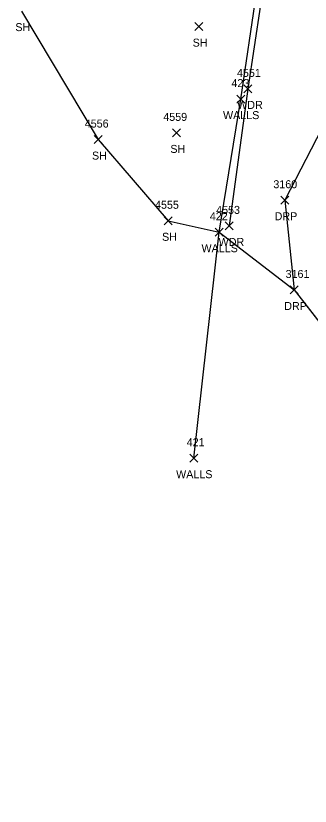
# Model space of a CAD drawing. Extents: x 1509053 to 1511576, y 400838 to 402572.
# Drawn here: x 1509486.6 to 1509560.1, y 401706.7 to 401904.1 of the extents above; entities that cross this region are included whole.
import ezdxf

# ---------------------------------------------------------------- set-up
doc = ezdxf.new("R2010")
doc.units = 0
for name, color, linetype in [('L_A', 7, 'Continuous'), ('L_I', 7, 'Continuous'), ('L_TIC', 7, 'Continuous'), ('LAWA', 7, 'Continuous'), ('LSOGP', 7, 'Continuous'), ('LWS', 7, 'Continuous'), ('R_A', 7, 'Continuous'), ('R_I', 7, 'Continuous'), ('R_TIC', 7, 'Continuous'), ('RDP', 7, 'Continuous')]:
    doc.layers.add(name, color=color, linetype=linetype)

msp = doc.modelspace()

# ---------------------------------------------------------------- linework, layer by layer
at = {"layer": 'L_TIC'}
for points in [[(1509531.26, 401900.37), (1509533.26, 401902.37)], [(1509533.26, 401900.37), (1509531.26, 401902.37)], [(1509543.51, 401884.82), (1509545.51, 401886.82)], [(1509545.51, 401884.82), (1509543.51, 401886.82)], [(1509541.8, 401882.27), (1509543.8, 401884.27)], [(1509543.8, 401882.27), (1509541.8, 401884.27)], [(1509525.69, 401873.83), (1509527.69, 401875.83)], [(1509527.69, 401873.83), (1509525.69, 401875.83)], [(1509506.12, 401872.16), (1509508.12, 401874.16)], [(1509508.12, 401872.16), (1509506.12, 401874.16)], [(1509523.62, 401851.88), (1509525.62, 401853.88)], [(1509525.62, 401851.88), (1509523.62, 401853.88)], [(1509538.88, 401850.6), (1509540.88, 401852.6)], [(1509540.88, 401850.6), (1509538.88, 401852.6)], [(1509536.41, 401849.03), (1509538.41, 401851.03)], [(1509538.41, 401849.03), (1509536.41, 401851.03)], [(1509530.07, 401792.59), (1509532.07, 401794.59)], [(1509532.07, 401792.59), (1509530.07, 401794.59)]]:
    msp.add_lwpolyline(points, dxfattribs=at)
at = {"layer": 'LAWA'}
msp.add_lwpolyline([(1509549.28, 401917.4), (1509544.51, 401885.82), (1509539.88, 401851.6)], dxfattribs=at)
at = {"layer": 'LSOGP'}
msp.add_lwpolyline([(1509487.97, 401905.25), (1509507.12, 401873.16), (1509524.62, 401852.88), (1509537.41, 401850.03), (1509556.14, 401835.6), (1509559.91, 401830.74), (1509563.69, 401825.89)], dxfattribs=at)
at = {"layer": 'LWS'}
msp.add_lwpolyline([(1509531.07, 401793.59), (1509537.41, 401850.03), (1509542.8, 401883.27), (1509546.66, 401909.78), (1509550.53, 401940.5), (1509554.91, 401970.83)], dxfattribs=at)
at = {"layer": 'R_TIC'}
for points in [[(1509552.74, 401857.01), (1509554.74, 401859.01)], [(1509554.74, 401857.01), (1509552.74, 401859.01)], [(1509555.14, 401834.6), (1509557.14, 401836.6)], [(1509557.14, 401834.6), (1509555.14, 401836.6)]]:
    msp.add_lwpolyline(points, dxfattribs=at)
at = {"layer": 'RDP'}
msp.add_lwpolyline([(1509572.43, 401913.76), (1509571.87, 401895.84), (1509563.03, 401875.91), (1509553.74, 401858.01), (1509556.14, 401835.6), (1509571.23, 401816.18), (1509583.76, 401803.06), (1509589.35, 401790.3), (1509589.12, 401773.24), (1509584.51, 401748.72), (1509580.76, 401730.09), (1509580.7, 401706.68)], dxfattribs=at)

# ---------------------------------------------------------------- texts
at = {"layer": 'L_A'}
for s, p in [('SH', (1509486.46, 401900.25)), ('SH', (1509530.75, 401896.37)), ('WDR', (1509541.87, 401880.82)), ('WALLS', (1509538.34, 401878.27)), ('SH', (1509525.18, 401869.83)), ('SH', (1509505.61, 401868.16)), ('SH', (1509523.11, 401847.88)), ('WDR', (1509537.24, 401846.6)), ('WALLS', (1509532.96, 401845.03)), ('WALLS', (1509526.62, 401788.59))]:
    msp.add_text(s, height=2, dxfattribs=at).set_placement(p)
at = {"layer": 'L_I'}
for s, p in [('4551', (1509541.82, 401888.82)), ('423', (1509540.44, 401886.27)), ('4559', (1509523.42, 401877.83)), ('4556', (1509503.81, 401876.16)), ('4555', (1509521.36, 401855.88)), ('4553', (1509536.62, 401854.6)), ('422', (1509535.05, 401853.03)), ('421', (1509529.28, 401796.59))]:
    msp.add_text(s, height=2, dxfattribs=at).set_placement(p)
at = {"layer": 'R_A'}
for p in [(1509551.23, 401853.01), (1509553.63, 401830.6)]:
    msp.add_text('DRP', height=2, dxfattribs=at).set_placement(p)
at = {"layer": 'R_I'}
for s, p in [('3160', (1509550.91, 401861.01)), ('3161', (1509553.97, 401838.6))]:
    msp.add_text(s, height=2, dxfattribs=at).set_placement(p)

doc.saveas('drawing.dxf')
